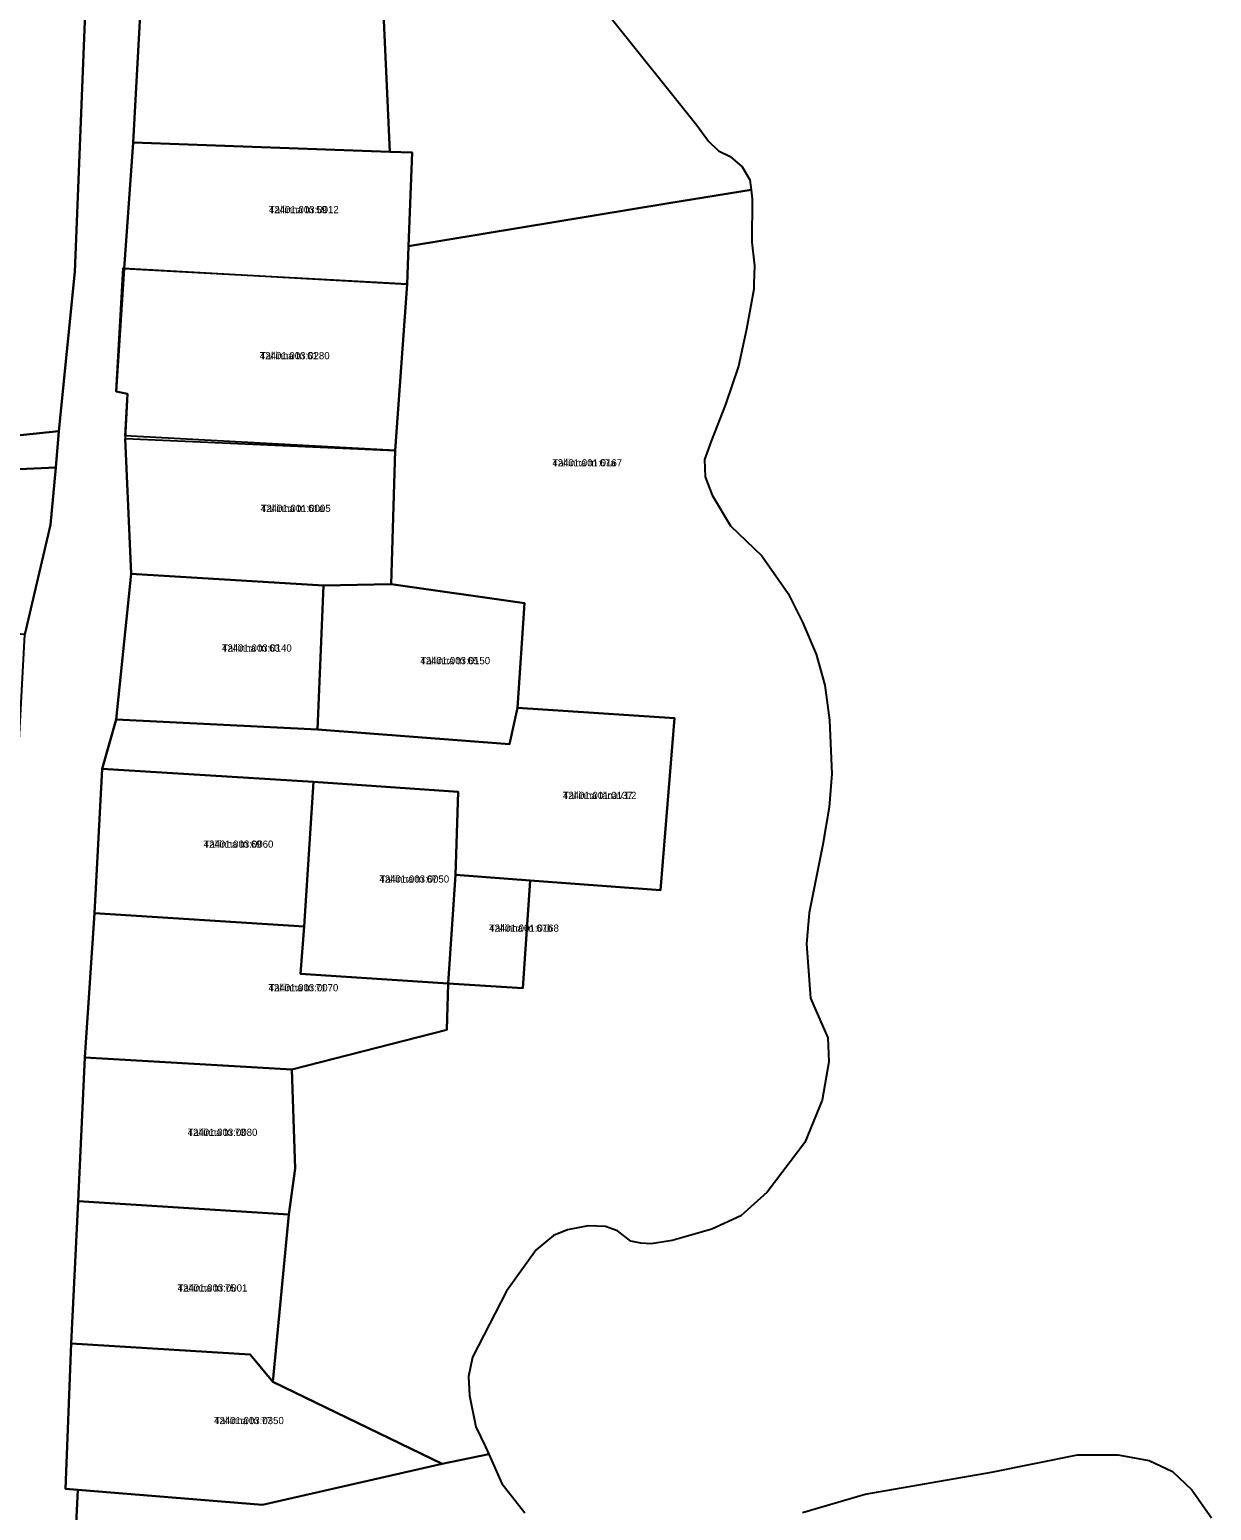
# Model space of a CAD drawing. Extents: x 595979 to 597983, y 6604231 to 6607350.
# Drawn here: x 597474.2 to 597719.8, y 6605161.4 to 6605469.2 of the extents above; entities that cross this region are included whole.
import ezdxf

# ---------------------------------------------------------------- set-up
doc = ezdxf.new("R2010")
doc.units = 0
for name, color, linetype in [('L_AADRESS', 7, 'Continuous'), ('PIIR', 7, 'Continuous'), ('TUNNUS', 7, 'Continuous')]:
    doc.layers.add(name, color=color, linetype=linetype)

msp = doc.modelspace()

# ---------------------------------------------------------------- linework, layer by layer
at = {"layer": 'PIIR'}
for points in [[(597487.25, 6605511.01), (597483.61, 6605418.8), (597480.24, 6605385.69), (597426.8, 6605380.15), (597425.53, 6605398.77), (597423.84, 6605411.85), (597382.25, 6605406.98), (597386.22, 6605375.09), (597383.41, 6605350.97), (597368.21, 6605349.13), (597261.05, 6605336.16), (597206.07, 6605392.81), (597206.99, 6605399.53), (597311.2, 6605456.81), (597316.36, 6605459.7), (597338.73, 6605470.54)], [(597491.74, 6604767.94), (597460.13, 6604897.15), (597453.23, 6604975.44), (597460.84, 6605133.45), (597461.82, 6605155.54), (597462.44, 6605169.92), (597464.18, 6605199.35), (597465.36, 6605215.89), (597466.32, 6605232.67), (597467.99, 6605256.4), (597471.01, 6605303.31), (597471.58, 6605313.69), (597473.22, 6605343.42), (597478.52, 6605366.25), (597479.63, 6605378.15), (597480.24, 6605385.69), (597483.61, 6605418.8), (597487.25, 6605511.01)], [(597498.55, 6605497.68), (597495.69, 6605445.75), (597493.85, 6605419.46), (597492.15, 6605393.93), (597494.55, 6605393.47), (597494.02, 6605384.17), (597495.31, 6605356.06), (597492.19, 6605325.76), (597489.28, 6605315.53), (597487.66, 6605285.55), (597485.7, 6605255.55), (597484.3, 6605225.65), (597482.84, 6605196.09), (597481.62, 6605165.89), (597484.23, 6605165.63), (597475.17, 6604980.33), (597478.02, 6604932.13), (597490.06, 6604855.41), (597496.29, 6604831.36)], [(597594.79, 6605471.88), (597612.87, 6605449.35), (597615.27, 6605445.97), (597617.37, 6605443.96), (597619.78, 6605442.79), (597622.29, 6605440.67), (597623.85, 6605437.93), (597624.12, 6605435.91), (597607.01, 6605433.08), (597552.93, 6605424.15), (597553.72, 6605443.64), (597549.02, 6605443.81), (597546.56, 6605498.49)], [(597475.17, 6604980.33), (597484.23, 6605165.63), (597522.61, 6605162.53), (597559.93, 6605171.08), (597569.63, 6605173.08), (597572.35, 6605166.96), (597577.13, 6605160.86)], [(597634.79, 6605160.93), (597647.84, 6605164.75), (597674.09, 6605169.34), (597691.99, 6605172.93), (597700.34, 6605172.91), (597706.85, 6605171.72), (597711.69, 6605169.48), (597715.72, 6605165.62), (597719.78, 6605159.82)]]:
    msp.add_lwpolyline(points, dxfattribs=at)
for points in [[(597498.55, 6605497.68), (597526.95, 6605497.69), (597546.56, 6605498.49), (597549.02, 6605443.81), (597495.69, 6605445.75)], [(597495.69, 6605445.75), (597549.02, 6605443.81), (597553.72, 6605443.64), (597552.93, 6605424.15), (597552.67, 6605416.29), (597493.85, 6605419.46)], [(597552.67, 6605416.29), (597552.93, 6605424.15), (597607.01, 6605433.08), (597624.12, 6605435.91), (597624.36, 6605434.04), (597624.31, 6605424.99), (597624.81, 6605420.05), (597624.71, 6605416.35), (597624.68, 6605415.21), (597623.16, 6605406.91), (597621.54, 6605399.24), (597618.81, 6605391.23), (597615.85, 6605383.61), (597614.47, 6605379.8), (597614.58, 6605376.2), (597616.06, 6605372.4), (597619.87, 6605366.05), (597626.33, 6605359.8), (597631.83, 6605351.97), (597634.79, 6605346.04), (597637.65, 6605339.38), (597639.45, 6605332.92), (597640.4, 6605325.62), (597640.92, 6605314.51), (597640.37, 6605307.57), (597639.02, 6605299.79), (597636.17, 6605285.61), (597635.64, 6605279.16), (597636.48, 6605267.83), (597640.08, 6605259.58), (597640.3, 6605254.6), (597638.92, 6605246.67), (597635.32, 6605237.88), (597627.49, 6605227.51), (597621.99, 6605222.64), (597615.99, 6605219.86), (597607.7, 6605217.45), (597603.36, 6605216.82), (597601.24, 6605216.93), (597599.13, 6605217.35), (597596.38, 6605219.47), (597593.84, 6605220.42), (597590.24, 6605220.52), (597586, 6605219.68), (597583.04, 6605218.51), (597579.44, 6605215.55), (597573.3, 6605206.98), (597566.21, 6605193.22), (597565.37, 6605189.2), (597565.58, 6605185.28), (597566.95, 6605178.72), (597568.96, 6605174.59), (597569.63, 6605173.08), (597559.93, 6605171.08), (597524.71, 6605188.07), (597528.07, 6605222.89), (597529.35, 6605232.42), (597528.69, 6605253.01), (597560.9, 6605261.29), (597561.14, 6605270.91), (597576.66, 6605269.92), (597578.21, 6605292.33), (597605.33, 6605290.32), (597608.2, 6605326.06), (597575.6, 6605328.17), (597577.04, 6605349.98), (597549.36, 6605353.92), (597550.17, 6605381.69)], [(597492.15, 6605393.93), (597493.63, 6605419.62), (597552.67, 6605416.29), (597550.17, 6605381.69), (597494.04, 6605384.74), (597494.55, 6605393.47)], [(597459.86, 6605377.24), (597435.08, 6605374.23), (597434.39, 6605358.51), (597433.85, 6605358.52), (597415.66, 6605359.08), (597394.83, 6605359.72), (597394.16, 6605349.5), (597392.39, 6605327.14), (597368.21, 6605349.13), (597383.41, 6605350.97), (597386.22, 6605375.09), (597426.8, 6605380.15), (597480.24, 6605385.69), (597479.63, 6605378.15)], [(597495.31, 6605356.06), (597494.02, 6605384.17), (597550.17, 6605381.69), (597549.36, 6605353.92), (597535.24, 6605353.66)], [(597435.08, 6605374.23), (597459.86, 6605377.24), (597479.63, 6605378.15), (597478.52, 6605366.25), (597473.22, 6605343.42), (597433.89, 6605346.38)], [(597495.31, 6605356.06), (597535.24, 6605353.66), (597534.04, 6605323.69), (597492.19, 6605325.76)], [(597535.24, 6605353.66), (597549.36, 6605353.92), (597577.04, 6605349.98), (597575.6, 6605328.17), (597573.91, 6605320.62), (597534.04, 6605323.69)], [(597562.72, 6605293.48), (597563.23, 6605310.75), (597533.18, 6605312.83), (597489.28, 6605315.53), (597492.19, 6605325.76), (597534.04, 6605323.69), (597573.91, 6605320.62), (597575.6, 6605328.17), (597608.2, 6605326.06), (597605.33, 6605290.32), (597578.21, 6605292.33)], [(597533.18, 6605312.83), (597531.25, 6605282.72), (597487.66, 6605285.55), (597489.28, 6605315.53)], [(597563.23, 6605310.75), (597562.72, 6605293.48), (597561.14, 6605270.91), (597530.52, 6605272.93), (597531.25, 6605282.72), (597533.18, 6605312.83)], [(597561.14, 6605270.91), (597562.72, 6605293.48), (597578.21, 6605292.33), (597576.66, 6605269.92)], [(597531.25, 6605282.72), (597530.52, 6605272.93), (597561.14, 6605270.91), (597560.9, 6605261.29), (597528.69, 6605253.01), (597485.7, 6605255.55), (597487.66, 6605285.55)], [(597528.69, 6605253.01), (597529.35, 6605232.42), (597528.07, 6605222.89), (597484.3, 6605225.65), (597485.7, 6605255.55)], [(597484.3, 6605225.65), (597528.07, 6605222.89), (597524.71, 6605188.07), (597520.04, 6605193.78), (597482.84, 6605196.09)], [(597520.04, 6605193.78), (597524.71, 6605188.07), (597559.93, 6605171.08), (597522.61, 6605162.53), (597484.23, 6605165.63), (597481.62, 6605165.89), (597482.84, 6605196.09)]]:
    msp.add_lwpolyline(points, close=True, dxfattribs=at)

# ---------------------------------------------------------------- texts
at = {"layer": 'L_AADRESS'}
for s, p in [('Tallinna tn 59', (597523.93, 6605431.02)), ('Tallinna tn 61', (597522.04, 6605400.66)), ('Tallinna tn 67a', (597582.82, 6605378.39)), ('Tallinna tn 61a', (597522.26, 6605368.92)), ('Tallinna tn 63', (597514.17, 6605339.88)), ('Tallinna tn 65', (597555.39, 6605337.27)), ('Tallinna tänav L2', (597585.02, 6605309.25)), ('Tallinna tn 69', (597510.35, 6605299.12)), ('Tallinna tn 67', (597546.88, 6605291.87)), ('Tallinna tn 67b', (597569.68, 6605281.66)), ('Tallinna tn 71', (597523.85, 6605269.28)), ('Tallinna tn 73', (597507.03, 6605239.22)), ('Tallinna tn 75', (597504.95, 6605206.86)), ('Tallinna tn 77', (597512.52, 6605179.31))]:
    msp.add_text(s, height=1.5, dxfattribs=at).set_placement(p)
at = {"layer": 'TUNNUS'}
for s, p in [('42401:003:0012', (597523.93, 6605431.02)), ('42401:003:0280', (597522.04, 6605400.66)), ('42401:001:0167', (597582.82, 6605378.39)), ('42401:001:0005', (597522.26, 6605368.92)), ('42401:003:0140', (597514.17, 6605339.88)), ('42401:003:0150', (597555.39, 6605337.27)), ('42401:001:0137', (597585.02, 6605309.25)), ('42401:003:0060', (597510.35, 6605299.12)), ('42401:003:0050', (597546.88, 6605291.87)), ('42401:001:0168', (597569.68, 6605281.66)), ('42401:003:0070', (597523.85, 6605269.28)), ('42401:003:0080', (597507.03, 6605239.22)), ('42401:003:0001', (597504.95, 6605206.86)), ('42401:003:0350', (597512.52, 6605179.31))]:
    msp.add_text(s, height=1.5, dxfattribs=at).set_placement(p)

doc.saveas('drawing.dxf')
